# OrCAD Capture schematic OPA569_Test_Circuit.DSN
size A; title: OPA569 Rail-to-Rail I/O, 2A POWER AMPLIFIER; rev: 1.1; note: Datasheet: SBOS264A EVM: N/A; note: Reference
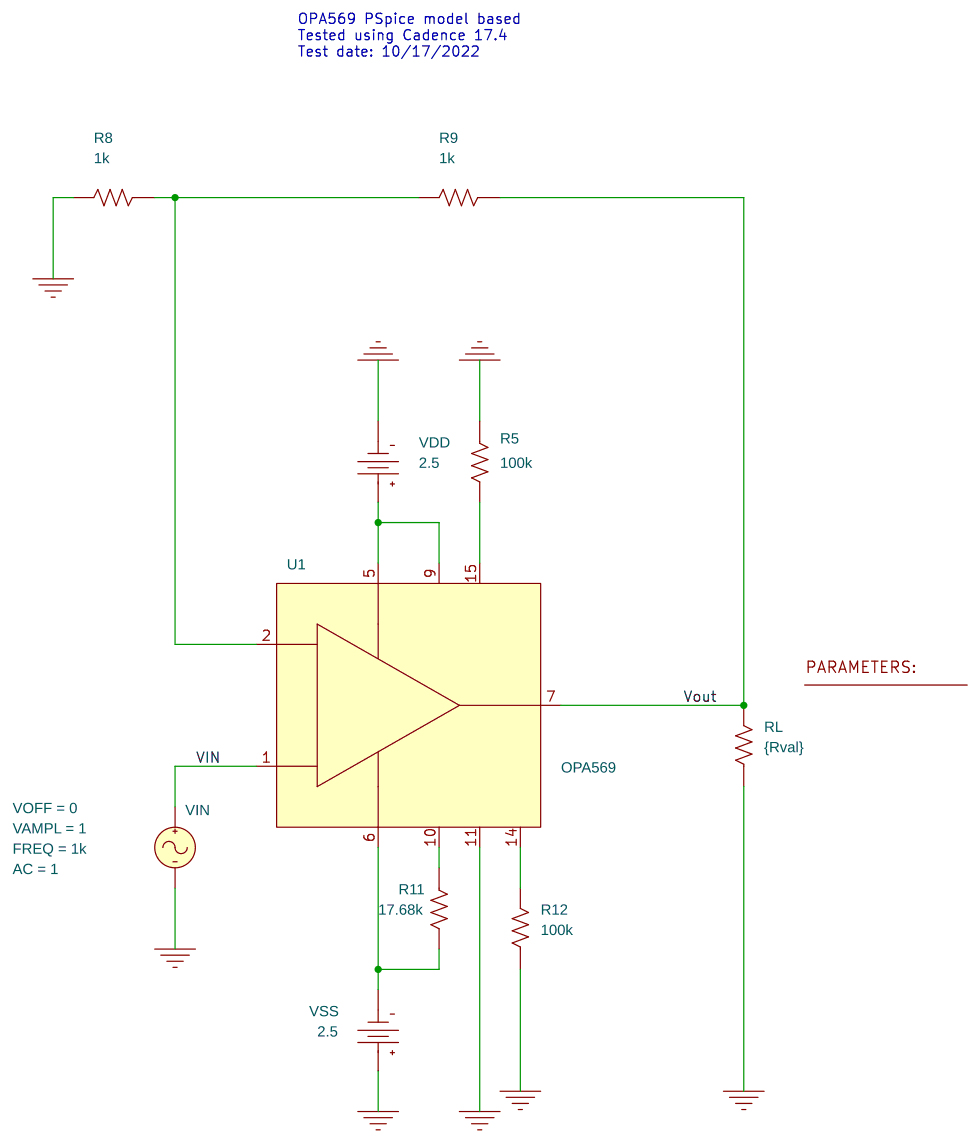
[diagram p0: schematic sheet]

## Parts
2  PARAM
R5  100k  [AX/RC05]
R8  1k  [AX/RC05]
R9  1k  [AX/RC05]
R11  17.68k  [AX/RC05]
R12  100k  [AX/RC05]
RL  {Rval}  [AX/RC05]
U1  OPA569
VDD  VDC
VIN  VSIN
VSS  VDC

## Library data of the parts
2 = PARAM: Rval: 5
R5 R8 R9 R11 R12 RL = R
U1 = OPA569
VDD VSS = VDC: DC: 2.5
VIN = VSIN: AC: 1; FREQ: 1k; VAMPL: 1; VOFF: 0

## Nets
VIN: U1.1(+) VIN.1(+)
0: R5.1 R8.2 R12.1 RL.1 U1.11(IMON) VDD.1(-) VIN.2(-) VSS.0(+)
Vout: R9.1 RL.2 U1.7(OUT)
N14328257: R8.1 R9.2 U1.2(-)
N14330360: U1.5(V+) U1.9(EN) VDD.0(+)
N14330364: R5.2 U1.15(TFLG)
N14330454: R12.2 U1.14(ILIMFLG)
N14332674: R11.2 U1.6(V-) VSS.1(-)
N14335805: R11.1 U1.10(ISET)

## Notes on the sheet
- OPA569 PSpice model based
  Tested using Cadence 17.4
  Test date: 10/17/2022
